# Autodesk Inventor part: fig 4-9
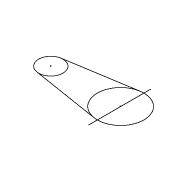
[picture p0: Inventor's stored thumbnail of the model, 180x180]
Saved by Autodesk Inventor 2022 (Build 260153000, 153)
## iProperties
Created: 2005-02
Part Number: fig 4-9
Document SubType Name: Modeling
Designer: CADCIM
Manufacturer: Standard
Standards Organization: Custom
Density: 1 g/cm^3
Material: Generic
Appearance: Default
Author: CADCIM
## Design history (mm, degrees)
sketch "Sketch1"
  geometry: L1 (-28.496, 15.735)-(10.446, 21.986); L2 (-28.503, 2.004)-(10.432, -4.291); L3 (12.58, 26.117)-(12.58, -9.642); A1 r 6.954 centre (-27.393, 8.869) between (-28.496, 15.735) and (-28.503, 2.004); A2 r 13.308 centre (12.555, 8.846) between (10.446, 21.986) and (10.432, -4.291)
  constraints: 6 end point, 4 point on circle, 4 tangent, 2 centre point, 1 vertical, 1 other
